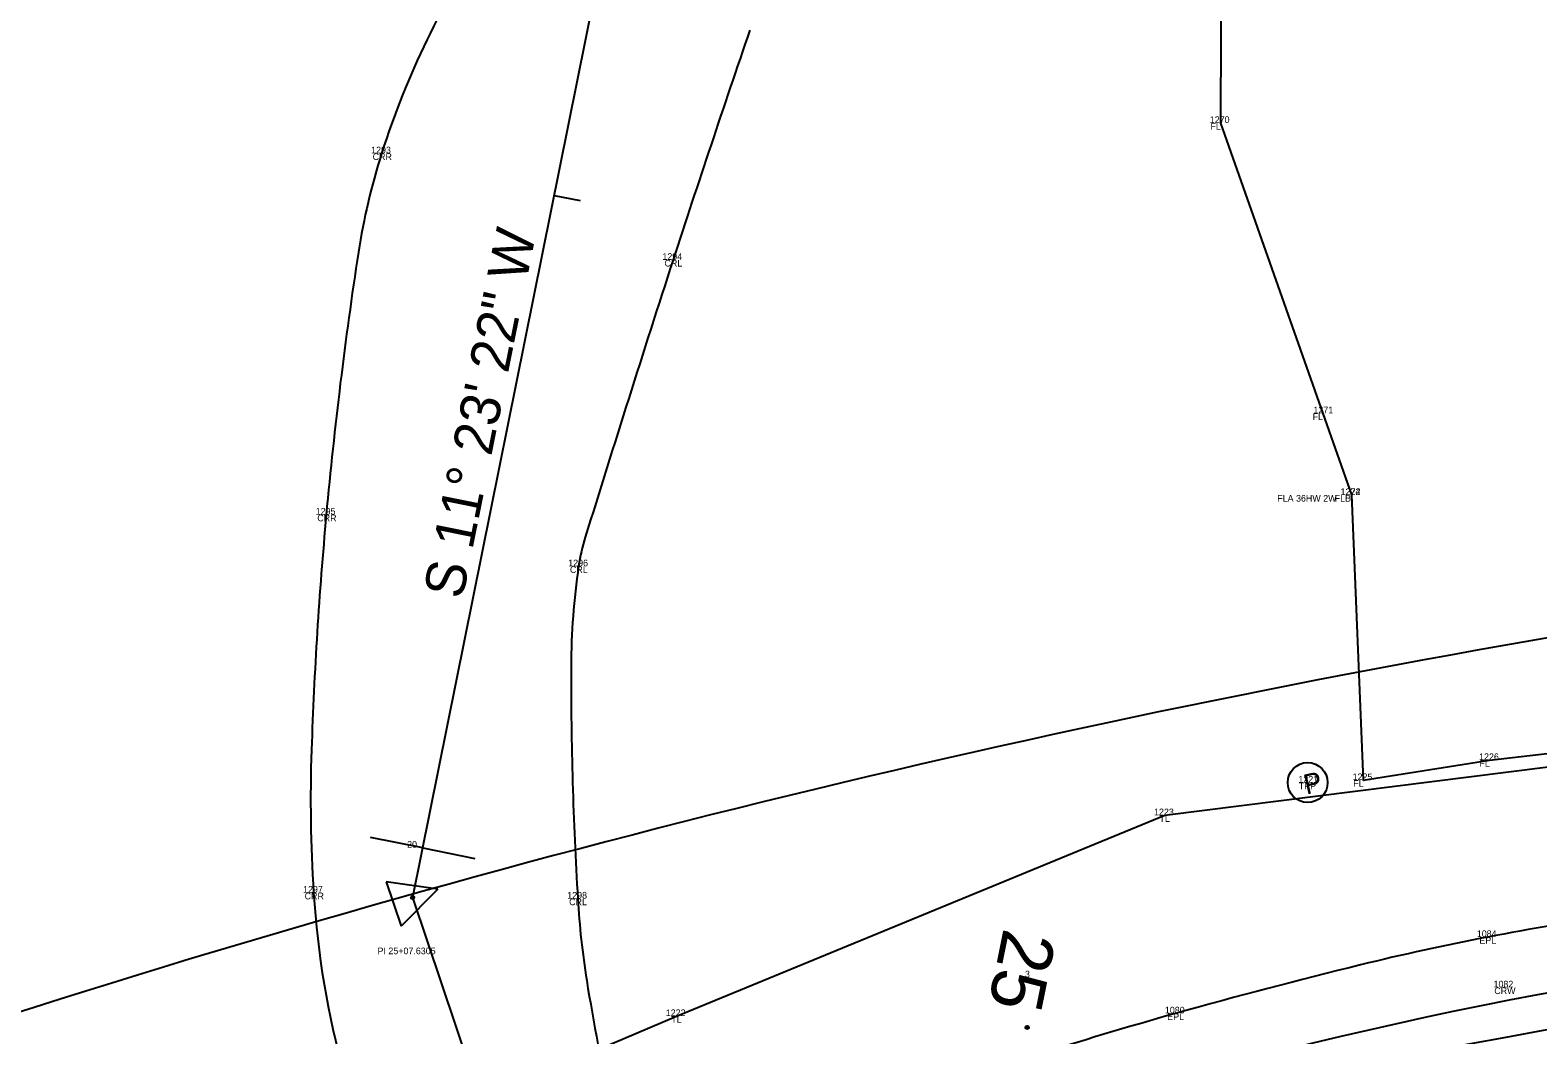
# Model space of a CAD drawing. Extents: x 1965498 to 1971309, y 1116335 to 1119906.
# Drawn here: x 1967747.3 to 1967973.9, y 1117914.3 to 1118065.2 of the extents above; entities that cross this region are included whole.
import ezdxf

# ---------------------------------------------------------------- set-up
doc = ezdxf.new("R2010")
doc.units = 0
for name, color, linetype in [('Level 12', 7, 'Continuous'), ('Level 21', 7, 'Continuous'), ('Level 33', 7, 'Continuous'), ('Level 50', 7, 'Continuous'), ('Level 51', 7, 'Continuous'), ('Level 53', 7, 'Continuous'), ('Level 58', 7, 'Continuous'), ('Level 59', 7, 'Continuous'), ('Level 60', 7, 'Continuous'), ('Level 61', 7, 'Continuous'), ('RD_DTM_BkLn2', 7, 'Continuous'), ('RD_DTM_Tri1', 7, 'Continuous'), ('RD_EX_Driveway', 7, 'Continuous'), ('RD_EX_H2O', 7, 'Continuous'), ('RD_EX_H2O_txCode', 7, 'Continuous'), ('RD_EX_Road', 7, 'Continuous'), ('RD_SMD_Locator', 7, 'Continuous'), ('RD_SMD_Misc', 7, 'Continuous')]:
    doc.layers.add(name, color=color, linetype=linetype)

msp = doc.modelspace()

# ---------------------------------------------------------------- linework, layer by layer
at = {"layer": 'Level 12'}
for p, q in [((1967834.04, 1118079.96), (1967804.81, 1117934.87)), ((1967804.81, 1117934.87), (1967825.19, 1117874.05))]:
    msp.add_line(p, q, dxfattribs=at)
for centre, radius in [((1967897.18, 1117915.38), 0.25), ((1967897.17, 1117915.38), 0.02), ((1967897.17, 1117915.38), 0.0001)]:
    msp.add_circle(centre, radius, dxfattribs=at)
at = {"layer": 'Level 33'}
msp.add_arc((1968266.61, 1116286.83), 1712.02, 94.56706, 111.99584, dxfattribs=at)
at = {"layer": 'Level 50'}
for centre in [(1967926.25, 1118051.25), (1967800.15, 1118046.69), (1967843.96, 1118030.69), (1967941.61, 1118007.63), (1967945.93, 1117995.37), (1967945.93, 1117995.37), (1967791.83, 1117992.41), (1967829.77, 1117984.65), (1967966.69, 1117955.54), (1967947.71, 1117952.52), (1967917.86, 1117947.25), (1967789.93, 1117935.61), (1967804.81, 1117934.87), (1967829.63, 1117934.73), (1967966.4, 1117928.95), (1967968.89, 1117921.38), (1967844.47, 1117917.07), (1967919.49, 1117917.47), (1967897.17, 1117915.38)]:
    msp.add_circle(centre, 0.001, dxfattribs=at)
at = {"layer": 'RD_DTM_BkLn2'}
for points in [[(1967920.92, 1118368.66), (1967937.87, 1118342.4), (1967954.81, 1118301.31), (1967965.67, 1118250.56), (1967963.61, 1118188.09), (1967935.71, 1118144.56), (1967926.43, 1118106.38), (1967926.25, 1118051.25), (1967941.61, 1118007.63), (1967945.93, 1117995.37)], [(1967945.93, 1117995.37), (1967947.71, 1117952.52), (1967966.69, 1117955.54), (1968009.98, 1117960.51), (1968062.77, 1117959.8), (1968105.6, 1117961.86), (1968158.55, 1117958.33), (1968214.15, 1117955.95), (1968422.33, 1117947.89), (1968537.53, 1117942.88)]]:
    msp.add_lwpolyline(points, dxfattribs=at)
at = {"layer": 'RD_DTM_Tri1'}
msp.add_lwpolyline([(1967422.03, 1117809.72), (1967453.38, 1117748.92), (1967559.8, 1117796.17), (1967844.47, 1117917.07), (1967917.86, 1117947.25), (1968009.67, 1117958.84), (1968061.48, 1117958.08), (1968105.8, 1117963.33), (1968158.86, 1117956.79), (1968212.37, 1117954.08), (1968423.16, 1117946.63), (1968536.42, 1117942.26)], dxfattribs=at)
at = {"layer": 'RD_EX_Driveway'}
for centre, radius, start, end in [((1967924.21, 1118007.05), 130.24, 146.084, 162.2789), ((1969955.94, 1117343.65), 2220.92, 161.04122, 161.97992), ((1967892.8, 1118017.09), 97.26, 162.2789, 171.2815), ((1968447.32, 1117932.05), 658.27, 171.28154, 174.73903), ((1970536.08, 1117154.93), 2830.98, 161.97992, 162.86471), ((1968396.68, 1117936.71), 607.41, 174.73903, 178.08012), ((1967859.17, 1117980.26), 29.73, 162.8647, 171.5072), ((1967932.18, 1117969.36), 103.55, 171.5072, 179.8469), ((1968385.41, 1117968.14), 556.78, 179.8469, 183.4407), ((1968012.41, 1117949.59), 222.93, 178.0801, 183.5965), ((1967922.97, 1117943.97), 133.3, 183.5965, 195.4685), ((1967954.76, 1117942.25), 125.36, 183.4407, 189.0928), ((1968136.99, 1117971.42), 309.91, 189.0928, 192.6866)]:
    msp.add_arc(centre, radius, start, end, dxfattribs=at)
at = {"layer": 'RD_EX_H2O'}
msp.add_circle((1967939.34, 1117952.16), 3, dxfattribs=at)
at = {"layer": 'RD_EX_H2O_txCode'}
msp.add_arc((1968266.61, 1116286.83), 1654.02, 97.99689, 110.59689, dxfattribs=at)
at = {"layer": 'RD_EX_Road'}
msp.add_arc((1968266.61, 1116286.83), 1637.02, 87.72663, 111.99584, dxfattribs=at)
at = {"layer": 'RD_SMD_Locator'}
for p, q in [((1967834.04, 1118079.96), (1967804.81, 1117934.87)), ((1967826.06, 1118040.38), (1967829.99, 1118039.59)), ((1967806.32, 1117942.35), (1967798.47, 1117943.93)), ((1967806.32, 1117942.35), (1967814.16, 1117940.77)), ((1967800.85, 1117937.24), (1967803.08, 1117930.6)), ((1967808.6, 1117936.14), (1967800.85, 1117937.24)), ((1967808.6, 1117936.14), (1967803.08, 1117930.6)), ((1967804.81, 1117934.87), (1967849.81, 1117800.6))]:
    msp.add_line(p, q, dxfattribs=at)
msp.add_circle((1967804.81, 1117934.87), 0.25, dxfattribs=at)
msp.add_arc((1968094.39, 1117277.53), 653.93, 87.72663, 111.99584, dxfattribs=at)
at = {"layer": 'RD_SMD_Misc'}
for centre, radius, start, end in [((1968039.2, 1117551.01), 384.88, 97.9635, 100.9026), ((1968040.96, 1117541.9), 394.16, 100.9026, 103.7451), ((1968149.84, 1117096.77), 852.41, 103.74512, 105.67793), ((1968090.83, 1117307.02), 634.04, 105.67793, 107.70681)]:
    msp.add_arc(centre, radius, start, end, dxfattribs=at)

# ---------------------------------------------------------------- texts
at = {"layer": 'Level 21'}
for s, height, rotation, p in [('S 11%%d 23\' 22" W', 6, 78.6104, (1967812.28, 1117979.56)), ('S 11%%d 23\' 22" W', 6, 78.6104, (1967812.28, 1117979.56)), ('25', 8, 258.6104, (1967893.69, 1117930.46)), ('25', 8, 258.6104, (1967893.69, 1117930.46))]:
    msp.add_text(s, height=height, rotation=rotation, dxfattribs=at).set_placement(p)
at = {"layer": 'Level 51'}
for s, p in [('20', (1967803.98, 1117942.37)), ('PI 25+07.6305', (1967799.53, 1117926.37)), ('3', (1967896.84, 1117922.88))]:
    msp.add_text(s, height=1, dxfattribs=at).set_placement(p)
at = {"layer": 'Level 53'}
for s, p in [('1084', (1967964.77, 1117928.95)), ('EPL', (1967965.15, 1117927.95)), ('1082', (1967967.28, 1117921.38)), ('CRW', (1967967.4, 1117920.38)), ('1080', (1967917.88, 1117917.47)), ('EPL', (1967918.24, 1117916.47))]:
    msp.add_text(s, height=1, dxfattribs=at).set_placement(p)
at = {"layer": 'Level 58'}
for s, p in [('1270', (1967924.63, 1118051.25)), ('FL', (1967924.73, 1118050.25)), ('FL', (1967940.09, 1118006.63)), ('1271', (1967940.21, 1118007.63)), ('1224', (1967944.29, 1117995.37)), ('1272', (1967944.31, 1117995.37)), ('FLA 36HW 2W', (1967934.77, 1117994.37)), ('FLB', (1967943.41, 1117994.37)), ('1226', (1967965.11, 1117955.54)), ('FL', (1967965.17, 1117954.54)), ('1225', (1967946.1, 1117952.52)), ('FL', (1967946.19, 1117951.52))]:
    msp.add_text(s, height=1, dxfattribs=at).set_placement(p)
at = {"layer": 'Level 59'}
for s, p in [('1221', (1967937.95, 1117952.16)), ('TPP', (1967938.01, 1117951.16))]:
    msp.add_text(s, height=1, dxfattribs=at).set_placement(p)
at = {"layer": 'Level 60'}
for s, p in [('CRR', (1967798.8, 1118045.69)), ('CRL', (1967842.66, 1118029.69)), ('CRR', (1967790.48, 1117991.41)), ('CRL', (1967828.46, 1117983.65)), ('CRR', (1967788.58, 1117934.61)), ('CRL', (1967828.33, 1117933.73))]:
    msp.add_text(s, height=1, dxfattribs=at).set_placement(p)
at = {"layer": 'Level 61'}
for s, p in [('1293', (1967798.57, 1118046.69)), ('1294', (1967842.35, 1118030.69)), ('1295', (1967790.24, 1117992.41)), ('1296', (1967828.2, 1117984.65)), ('1223', (1967916.25, 1117947.25)), ('TL', (1967917.07, 1117946.25)), ('1297', (1967788.34, 1117935.61)), ('1298', (1967828.05, 1117934.73)), ('1222', (1967842.86, 1117917.07)), ('TL', (1967843.69, 1117916.07))]:
    msp.add_text(s, height=1, dxfattribs=at).set_placement(p)
at = {"layer": 'RD_EX_H2O'}
msp.add_text('P', height=3, rotation=12.9494, dxfattribs=at).set_placement((1967939.15, 1117950.34))

doc.saveas('drawing.dxf')
